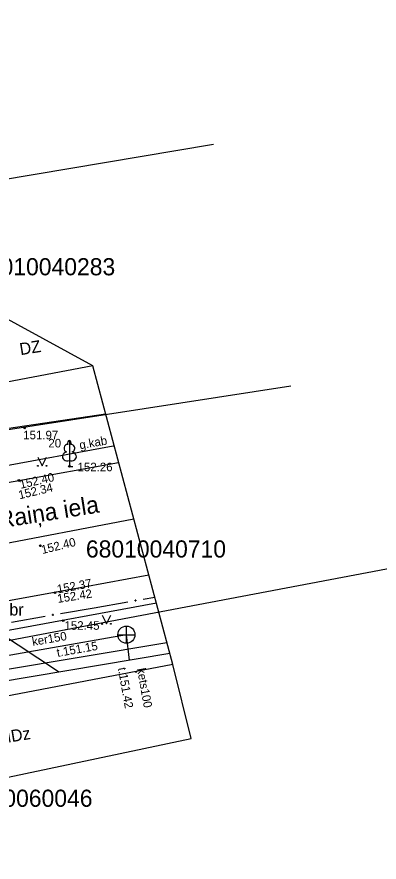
# Model space of a CAD drawing. Extents: x 728710 to 728960, y 272811 to 273475.
# Drawn here: x 728865.12 to 728886.27, y 272848.62 to 272897.93 of the extents above; entities that cross this region are included whole.
import ezdxf

# ---------------------------------------------------------------- set-up
doc = ezdxf.new("R2010")
doc.units = 0
for name, color, linetype in [('Level 17', 7, 'Continuous'), ('Level 21', 7, 'Continuous'), ('Level 23', 7, 'Continuous'), ('Level 25', 7, 'Continuous'), ('Level 29', 7, 'Continuous'), ('Level 3', 7, 'Continuous'), ('Level 38', 7, 'Continuous'), ('Level 4', 7, 'Continuous'), ('Level 48', 7, 'Continuous'), ('Level 53', 7, 'Continuous'), ('Level 54', 7, 'Continuous'), ('Level 57', 7, 'Continuous'), ('Level 58', 7, 'Continuous'), ('Level 59', 7, 'Continuous'), ('Level 60', 7, 'Continuous'), ('RAMI_UZMR_####_####_#', 7, 'Continuous'), ('RELJ_NOGA_####_####_#', 7, 'Continuous'), ('ROBZ_ELEM_####_####_#', 7, 'Continuous'), ('ROBZ_KADS_####_TKST_#', 7, 'Continuous'), ('ROBZ_UZMR_####_####_#', 7, 'Continuous'), ('TERT_KONT_####_####_#', 7, 'Continuous')]:
    doc.layers.add(name, color=color, linetype=linetype)

msp = doc.modelspace()

# ---------------------------------------------------------------- linework, layer by layer
at = {"layer": 'Level 17'}
msp.add_line((728867.556, 272859.717), (728858.084, 272865.975), dxfattribs=at)
msp.add_lwpolyline([(728871.949, 272868.624), (728863.38, 272866.993)], dxfattribs=at)
at = {"layer": 'Level 21'}
for p, q in [((728843.349, 272867.906), (728870.741, 272872.901)), ((728870.741, 272872.901), (728870.799, 272872.911))]:
    msp.add_line(p, q, dxfattribs=at)
at = {"layer": 'Level 23'}
msp.add_lwpolyline([(728871.694, 272860.411), (728871.514, 272861.89), (728857.554, 272859.424), (728857.791, 272858.081)], dxfattribs=at)
at = {"layer": 'Level 25'}
for p, q in [((728869.633, 272863.463), (728871.604, 272863.807)), ((728872.49, 272863.961), (728873.167, 272864.079)), ((728867.663, 272863.119), (728869.633, 272863.463)), ((728864.806, 272862.621), (728866.777, 272862.965))]:
    msp.add_line(p, q, dxfattribs=at)
for centre in [(728872.047, 272863.884), (728867.22, 272863.042)]:
    msp.add_circle(centre, 0.025, dxfattribs=at)
for centre, start, end in [((728872.047, 272863.884), 0, 180), ((728872.047, 272863.884), 180, 0), ((728867.22, 272863.042), 0, 180), ((728867.22, 272863.042), 180, 0)]:
    msp.add_arc(centre, 0.025, start, end, dxfattribs=at)
at = {"layer": 'Level 29'}
for points in [[(728871.514, 272861.39), (728871.514, 272862.39)], [(728871.014, 272861.89), (728872.014, 272861.89)]]:
    msp.add_lwpolyline(points, dxfattribs=at)
msp.add_circle((728871.514, 272861.89), 0.5, dxfattribs=at)
at = {"layer": 'Level 3'}
for p, q in [((728862.994, 272873.696), (728870.299, 272874.777)), ((728863.836, 272859.094), (728874.045, 272860.805))]:
    msp.add_line(p, q, dxfattribs=at)
at = {"layer": 'Level 38'}
for p, q in [((728865.233, 272870.887), (728871.06, 272871.941)), ((728869.037, 272864.687), (728872.816, 272865.387)), ((728863.571, 272863.69), (728869.037, 272864.687))]:
    msp.add_line(p, q, dxfattribs=at)
msp.add_lwpolyline([(728857.811, 272869.575), (728865.233, 272870.887)], dxfattribs=at)
at = {"layer": 'Level 4'}
for p, q in [((728873.262, 272863.724), (728863.05, 272861.839)), ((728863.798, 272859.753), (728873.877, 272861.43))]:
    msp.add_line(p, q, dxfattribs=at)
at = {"layer": 'Level 48'}
for centre in [(728865.578, 272873.958), (728868.186, 272871.713), (728865.233, 272870.887), (728866.491, 272867.081), (728867.347, 272864.335), (728867.827, 272862.708)]:
    msp.add_circle(centre, 0.05, dxfattribs=at)
at = {"layer": 'RAMI_UZMR_####_####_#'}
msp.add_lwpolyline([(728830.483, 272947.485), (728837.542, 272895.947), (728841.965, 272873.125), (728830.264, 272869.701), (728833.902, 272855.704), (728841.107, 272848.625), (728875.302, 272855.836), (728874.221, 272860.146), (728869.548, 272877.58), (728863.702, 272880.76), (728862.157, 272893.095), (728861.3, 272900.225)], dxfattribs=at)
at = {"layer": 'ROBZ_ELEM_####_####_#'}
for points in [[(728869.548, 272877.58), (728859.497, 272875.667)], [(728874.221, 272860.146), (728855.946, 272856.668), (728834.798, 272852.259)]]:
    msp.add_lwpolyline(points, dxfattribs=at)
at = {"layer": 'ROBZ_UZMR_####_####_#'}
for p, q in [((728876.602, 272890.484), (728856.77, 272887.17)), ((728858.708, 272872.952), (728881.106, 272876.418)), ((728902.328, 272868.666), (728847.507, 272858.293))]:
    msp.add_line(p, q, dxfattribs=at)
at = {"layer": 'TERT_KONT_####_####_#'}
for p, q in [((728866.351, 272872.242), (728866.601, 272871.742)), ((728866.601, 272871.742), (728866.851, 272872.242)), ((728868.186, 272872.06), (728868.186, 272871.713)), ((728868.186, 272871.713), (728868.386, 272871.713)), ((728870.104, 272863.023), (728870.354, 272862.523)), ((728870.354, 272862.523), (728870.604, 272863.023))]:
    msp.add_line(p, q, dxfattribs=at)
for points in [[(728868.186, 272873.213), (728868.186, 272872.06)], [(728868.276, 272872.981), (728868.275, 272872.982)]]:
    msp.add_lwpolyline(points, dxfattribs=at)
for centre, radius in [((728866.351, 272871.742), 0.028), ((728866.851, 272871.742), 0.0263), ((728870.104, 272862.523), 0.028), ((728870.604, 272862.523), 0.0263)]:
    msp.add_circle(centre, radius, dxfattribs=at)
for centre, major_axis, ratio, start_param, end_param in [((728868.186, 272873.064), (0, -0.15), 0.707107, 3.14537, 5.287485), ((728868.186, 272873.064), (0, -0.15), 0.707107, 0.995701, 3.137816), ((728868.058, 272872.769), (-0.039, -0.212), 0.861323, 3.141593, 6.283185), ((728868.314, 272872.769), (0.039, -0.212), 0.861323, 0, 3.141593), ((728868.096, 272872.306), (0.307, 0.095), 0.814445, 1.570796, 4.752015), ((728868.276, 272872.306), (-0.307, 0.095), 0.814445, 1.531171, 4.712389)]:
    msp.add_ellipse(centre, major_axis=major_axis, ratio=ratio, start_param=start_param, end_param=end_param, dxfattribs=at)

# ---------------------------------------------------------------- texts
at = {"layer": 'Level 53'}
msp.add_text('g.kab', height=0.5, rotation=10.3336, dxfattribs=at).set_placement((728868.812, 272872.702))
at = {"layer": 'Level 54'}
msp.add_text('Raiņa iela', height=1, rotation=9.0659, dxfattribs=at).set_placement((728864.097, 272868.087))
at = {"layer": 'Level 57'}
for s, p in [(' 151.97', (728865.305, 272873.291)), (' 152.26', (728868.477, 272871.426)), ('152.45', (728867.9, 272862.177))]:
    msp.add_text(s, height=0.5, dxfattribs=at).set_placement(p)
for s, rotation, p in [('152.40', 13.0787, (728865.346, 272870.4)), ('152.34', 13.4228, (728865.275, 272869.788)), ('152.40', 13.5865, (728866.608, 272866.595)), ('152.37', 10.3498, (728867.511, 272864.298)), ('152.42', 8.9544, (728867.519, 272863.743))]:
    msp.add_text(s, height=0.5, rotation=rotation, dxfattribs=at).set_placement(p)
at = {"layer": 'Level 58'}
msp.add_text('bbr', height=0.7, dxfattribs=at).set_placement((728864.163, 272863.011))
at = {"layer": 'Level 59'}
for s, rotation, p in [('DZ', 9.099, (728865.337, 272878.196)), ('2MDz', 9.514, (728863.552, 272855.41))]:
    msp.add_text(s, height=0.7, rotation=rotation, dxfattribs=at).set_placement(p)
at = {"layer": 'Level 60'}
for s, rotation, p in [('ker150', 10.018, (728866.05, 272861.23)), ('t.151.15', 10.018, (728867.494, 272860.591)), ('t.151.42', 280.018, (728871.014, 272859.941)), ('ķets100', 280.018, (728872.13, 272859.901))]:
    msp.add_text(s, height=0.5, rotation=rotation, dxfattribs=at).set_placement(p)
at = {"layer": 'RELJ_NOGA_####_####_#'}
msp.add_text('20', height=0.5, dxfattribs=at).set_placement((728866.957, 272872.814))
at = {"layer": 'ROBZ_KADS_####_TKST_#'}
for s, p in [('68010040283', (728862.68, 272882.858)), ('68010040710', (728869.15, 272866.394)), ('68010060046', (728861.354, 272851.851))]:
    msp.add_text(s, height=1, dxfattribs=at).set_placement(p)

doc.saveas('drawing.dxf')
